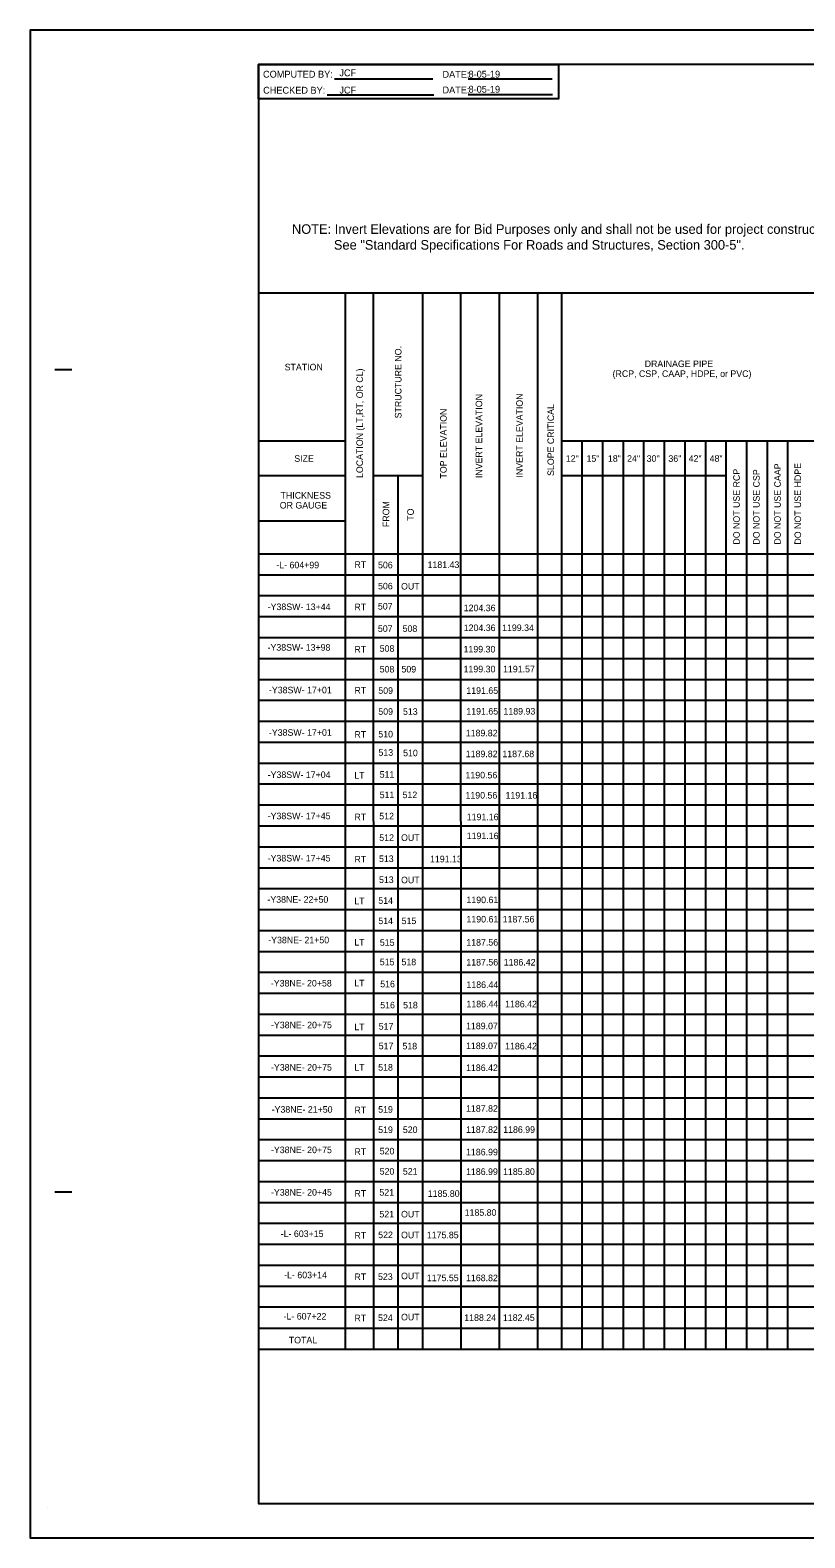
# Model space of a CAD drawing. Extents: x 809447 to 814738, y 647528 to 651206.
# Drawn here: x 811255 to 811820, y 650017 to 651117 of the extents above; entities that cross this region are included whole.
import ezdxf

# ---------------------------------------------------------------- set-up
doc = ezdxf.new("R2010")
doc.units = 0
doc.layers.add('Default', color=7, linetype='Continuous')

msp = doc.modelspace()

# ---------------------------------------------------------------- linework, layer by layer
at = {"layer": 'Default'}
for p, q in [((811476.8, 651081.5), (811548.4, 651081.5)), ((811574.2, 651081.4), (811635.6, 651081.4)), ((811471.4, 651069.8), (811549.1, 651069.8)), ((811574.3, 651069.9), (811635.7, 651069.9)), ((812921.2, 650925.1), (811421.2, 650925)), ((811484.8, 650154.3), (811484.8, 650925)), ((811505.4, 650154.3), (811505.3, 650925)), ((811541.1, 650154.3), (811541.1, 650925)), ((811569.1, 650154.3), (811569, 650925)), ((811597.1, 650154.3), (811597, 650925)), ((811625, 650154.3), (811625, 650925)), ((811642.5, 650154.3), (811642.5, 650925)), ((811272.7, 650869.4), (811285.2, 650869.4)), ((811484.8, 650817.1), (811421.2, 650817.1)), ((812160, 650817.2), (811642.5, 650817.1)), ((811657.5, 650154.3), (811657.5, 650817.1)), ((811672.5, 650154.3), (811672.5, 650817.1)), ((811687.5, 650154.3), (811687.5, 650817.1)), ((811702.5, 650154.3), (811702.5, 650817.1)), ((811717.5, 650154.3), (811717.5, 650817.1)), ((811732.5, 650154.3), (811732.5, 650817.1)), ((811747.5, 650154.3), (811747.5, 650817.1)), ((811762.5, 650154.3), (811762.5, 650817.1)), ((811777.5, 650154.3), (811777.5, 650817.1)), ((811792.5, 650154.3), (811792.5, 650817.1)), ((811807.5, 650154.3), (811807.5, 650817.1)), ((811484.8, 650791.7), (811421.2, 650791.7)), ((811541.1, 650791.7), (811505.3, 650791.7)), ((811523.3, 650154.3), (811523.2, 650791.7)), ((811762.5, 650791.8), (811642.5, 650791.7)), ((811484.8, 650758.6), (811421.2, 650758.6)), ((812921.2, 650734.7), (811421.2, 650734.7)), ((812921.2, 650719.4), (811421.2, 650719.4)), ((812921.2, 650704.1), (811421.2, 650704.1)), ((812921.2, 650688.9), (811421.2, 650688.9)), ((812921.2, 650673.6), (811421.2, 650673.6)), ((812921.2, 650658.3), (811421.2, 650658.3)), ((812921.2, 650643), (811421.2, 650643)), ((812921.2, 650627.8), (811421.2, 650627.8)), ((812921.2, 650612.5), (811421.2, 650612.5)), ((812921.2, 650597.3), (811421.2, 650597.3)), ((812921.2, 650582), (811421.2, 650582)), ((812921.2, 650566.7), (811421.2, 650566.7)), ((812921.2, 650551.5), (811421.2, 650551.5)), ((812921.2, 650536.2), (811421.2, 650536.2)), ((812921.2, 650520.9), (811421.2, 650520.9)), ((812921.2, 650505.6), (811421.2, 650505.6)), ((812921.2, 650490.4), (811421.2, 650490.4)), ((812921.2, 650475.1), (811421.2, 650475.1)), ((812921.2, 650459.8), (811421.2, 650459.8)), ((812921.2, 650444.5), (811421.2, 650444.5)), ((812921.2, 650429.3), (811421.2, 650429.3)), ((812921.2, 650414), (811421.2, 650414)), ((812921.2, 650398.8), (811421.2, 650398.8)), ((812921.2, 650383.5), (811421.2, 650383.5)), ((812921.2, 650368.3), (811421.2, 650368.3)), ((812921.2, 650353), (811421.2, 650353)), ((812921.2, 650337.8), (811421.2, 650337.8)), ((812921.2, 650322.5), (811421.2, 650322.5)), ((812921.2, 650307.2), (811421.2, 650307.2)), ((812921.2, 650291.9), (811421.2, 650291.9)), ((812921.2, 650276.7), (811421.2, 650276.7)), ((811272.7, 650269.4), (811285.2, 650269.4)), ((812921.2, 650261.4), (811421.2, 650261.4)), ((812921.2, 650246.2), (811421.2, 650246.2)), ((812921.2, 650230.9), (811421.2, 650230.9)), ((812921.2, 650215.7), (811421.2, 650215.7)), ((812921.2, 650200.4), (811421.2, 650200.4)), ((812921.2, 650185.2), (811421.2, 650185.2)), ((812921.2, 650169.6), (811421.2, 650169.6)), ((812921.2, 650154.3), (811421.2, 650154.3)), ((812921.2, 650154.3), (811421.2, 650154.3)), ((811267.7, 650039.4), (811267.7, 650039.4)), ((811421.2, 650041.9), (811421.2, 650041.9)), ((811421.2, 650041.9), (811421.2, 650041.9)), ((811421.2, 650041.9), (811421.2, 650041.9)), ((811421.2, 650041.9), (811421.2, 650041.9)), ((811421.2, 650041.9), (811421.2, 650041.9)), ((811421.2, 650041.9), (811421.2, 650041.9)), ((811421.2, 650041.9), (811421.2, 650041.9)), ((811421.2, 650041.9), (811421.2, 650041.9)), ((811421.2, 650041.9), (811421.2, 650041.9)), ((811254.7, 650016.9), (811254.7, 650016.9))]:
    msp.add_line(p, q, dxfattribs=at)
for points in [[(812938.7, 651116.9), (811254.7, 651116.9), (811254.7, 650016.9), (812938.7, 650016.9)], [(812921.2, 651091.9), (811421.2, 651091.9), (811421.2, 650041.9), (812921.2, 650041.9)], [(811421.2, 651091.9), (811640.2, 651091.9), (811640.2, 651066.9), (811421.2, 651066.9)]]:
    msp.add_lwpolyline(points, close=True, dxfattribs=at)

# ---------------------------------------------------------------- texts
for s, height, rotation, p in [('COMPUTED BY:', 5, 360, (811424.6, 651082.3)), ('JCF', 5, 360, (811480.3, 651083.3)), ('DATE:', 5, 360, (811555.5, 651082.2)), ('CHECKED BY:', 5, 360, (811424.7, 651070.6)), ('JCF', 5, 360, (811480.3, 651070.7)), ('DATE:', 5, 360, (811555.5, 651070.8)), ('STRUCTURE NO.', 4.8, 90, (811525.6, 650833.7)), ('STATION', 4.8, 360, (811440.4, 650868.7)), ('LOCATION (LT,RT, OR CL)', 4.8, 90, (811497.5, 650790.2)), ('INVERT ELEVATION', 4.8, 90, (811584.5, 650790.1)), ('INVERT ELEVATION', 4.8, 90, (811614.1, 650790.5)), ('TOP ELEVATION', 4.8, 90, (811558.6, 650789.8)), ('SLOPE CRITICAL', 4.8, 90, (811636.9, 650791.7)), ('DO NOT USE RCP', 4.8, 90, (811772.4, 650741.6)), ('DO NOT USE CSP', 4.8, 90, (811786.9, 650741.6)), ('DO NOT USE CAAP', 4.8, 90, (811802.3, 650741.6)), ('DO NOT USE HDPE', 4.8, 90, (811817.1, 650741.6)), ('FROM', 4.8, 90, (811516.7, 650754.4)), ('TO', 4.8, 90, (811534.6, 650759))]:
    msp.add_text(s, height=height, rotation=rotation, dxfattribs=at).set_placement(p)
for s, height, p in [('8-05-19', 5, (811574.5, 651082.3)), ('8-05-19', 5, (811574.5, 651071.3)), ('NOTE: Invert Elevations are for Bid Purposes only and shall not be used for project construction stakeout.', 7, (811445.7, 650968.3)), ('See "Standard Specifications For Roads and Structures, Section 300-5".', 7, (811476.3, 650956.8)), ('DRAINAGE PIPE', 4.8, (811703, 650871.1)), ('(RCP, CSP, CAAP, HDPE, or PVC)', 4.8, (811679.6, 650863.9)), ('SIZE', 4.8, (811447.4, 650802)), ('12"', 4.8, (811645.5, 650802)), ('15"', 4.8, (811660.6, 650802)), ('18"', 4.8, (811676.2, 650802)), ('24"', 4.8, (811690.2, 650802)), ('30"', 4.8, (811704.5, 650802)), ('36"', 4.8, (811720.3, 650802)), ('42"', 4.8, (811735.1, 650802)), ('48"', 4.8, (811750.4, 650802)), ('OR GAUGE', 4.8, (811436.8, 650767.9)), ('THICKNESS', 4.8, (811437.4, 650775.1)), ('-L- 604+99', 4.8, (811434.3, 650724.3)), ('RT', 4.8, (811491.3, 650724.6)), ('506', 4.8, (811508.5, 650724.3)), ('1181.43', 4.8, (811544.6, 650724.5)), ('506', 4.8, (811508.5, 650708.9)), ('OUT', 4.8, (811525.3, 650708.8)), ('-Y38SW- 13+44', 4.8, (811428, 650693.8)), ('RT', 4.8, (811491.3, 650693.7)), ('507', 4.8, (811508.4, 650694.2)), ('1204.36', 4.8, (811571, 650693)), ('1204.36', 4.8, (811571, 650678.5)), ('1199.34', 4.8, (811599, 650678.5)), ('507', 4.8, (811508.4, 650677.9)), ('508', 4.8, (811526.4, 650677.9)), ('-Y38SW- 13+98', 4.8, (811427.9, 650664.2)), ('RT', 4.8, (811491.3, 650662.8)), ('508', 4.8, (811509.7, 650663.4)), ('1199.30', 4.8, (811570.9, 650662.9)), ('508', 4.8, (811509.7, 650648.3)), ('509', 4.8, (811525.6, 650648.3)), ('1199.30', 4.8, (811570.9, 650648.4)), ('1191.57', 4.8, (811599.7, 650648.4)), ('-Y38SW- 17+01', 4.8, (811428.9, 650633.1)), ('RT', 4.8, (811491.3, 650632.9)), ('509', 4.8, (811508.7, 650632.7)), ('1191.65', 4.8, (811572.9, 650632.7)), ('509', 4.8, (811508.7, 650617.4)), ('513', 4.8, (811526.7, 650617.4)), ('1191.65', 4.8, (811572.9, 650617.6)), ('1189.93', 4.8, (811600, 650617.6)), ('-Y38SW- 17+01', 4.8, (811428.9, 650602.1)), ('1189.82', 4.8, (811572.5, 650601.7)), ('RT', 4.8, (811491.3, 650600.7)), ('510', 4.8, (811508.7, 650600.9)), ('513', 4.8, (811508.8, 650587.5)), ('510', 4.8, (811526.8, 650587.2)), ('1189.82', 4.8, (811572.5, 650586.5)), ('1187.68', 4.8, (811599.2, 650586.5)), ('-Y38SW- 17+04', 4.8, (811428, 650571.3)), ('LT', 4.8, (811491.2, 650570.9)), ('511', 4.8, (811509.7, 650571.5)), ('1190.56', 4.8, (811572.3, 650571)), ('511', 4.8, (811509.7, 650556.6)), ('512', 4.8, (811526.4, 650556.6)), ('1190.56', 4.8, (811572.3, 650556.3)), ('1191.16', 4.8, (811601.5, 650556.3)), ('-Y38SW- 17+45', 4.8, (811428, 650541.2)), ('RT', 4.8, (811491.3, 650540.5)), ('512', 4.8, (811509.4, 650541.1)), ('1191.16', 4.8, (811573.2, 650540.5)), ('512', 4.8, (811509.4, 650525.4)), ('OUT', 4.8, (811525.3, 650525.4)), ('1191.16', 4.8, (811573.2, 650526.7)), ('-Y38SW- 17+45', 4.8, (811428, 650510.4)), ('RT', 4.8, (811491.3, 650509.7)), ('513', 4.8, (811509.2, 650510)), ('1191.13', 4.8, (811546.4, 650509.8)), ('513', 4.8, (811509.2, 650494.7)), ('OUT', 4.8, (811525.3, 650494.5)), ('-Y38NE- 22+50', 4.8, (811427.8, 650480.3)), ('LT', 4.8, (811491.2, 650479.2)), ('514', 4.8, (811508.7, 650479.5)), ('1190.61', 4.8, (811573, 650480)), ('514', 4.8, (811508.7, 650464.7)), ('515', 4.8, (811525.7, 650464.7)), ('1190.61', 4.8, (811573, 650465.9)), ('1187.56', 4.8, (811599.4, 650465.9)), ('-Y38NE- 21+50', 4.8, (811428.4, 650450.7)), ('LT', 4.8, (811491.2, 650449.1)), ('515', 4.8, (811509.8, 650448.9)), ('1187.56', 4.8, (811572.9, 650449)), ('515', 4.8, (811509.8, 650434.7)), ('518', 4.8, (811525.6, 650434.7)), ('1187.56', 4.8, (811572.9, 650434.5)), ('1186.42', 4.8, (811600.2, 650434.5)), ('-Y38NE- 20+58', 4.8, (811430.3, 650419.2)), ('LT', 4.8, (811491.2, 650419.3)), ('516', 4.8, (811510.1, 650418.6)), ('1186.44', 4.8, (811573, 650418.1)), ('516', 4.8, (811510.1, 650403.2)), ('518', 4.8, (811526.8, 650403.2)), ('1186.44', 4.8, (811573, 650404)), ('1186.42', 4.8, (811601.2, 650404)), ('-Y38NE- 20+75', 4.8, (811430.4, 650388.7)), ('LT', 4.8, (811491.2, 650387.3)), ('517', 4.8, (811509, 650387.7)), ('1189.07', 4.8, (811572.7, 650388)), ('517', 4.8, (811509, 650373.4)), ('518', 4.8, (811526.3, 650373.3)), ('1189.07', 4.8, (811572.7, 650373.5)), ('1186.42', 4.8, (811601.2, 650373.3)), ('-Y38NE- 20+75', 4.8, (811430.4, 650357.8)), ('LT', 4.8, (811491.2, 650357.8)), ('518', 4.8, (811508.6, 650357.8)), ('1186.42', 4.8, (811572.7, 650357.5)), ('-Y38NE- 21+50', 4.8, (811430.9, 650327.1)), ('RT', 4.8, (811491.3, 650326.7)), ('519', 4.8, (811508.6, 650327.1)), ('1187.82', 4.8, (811572.7, 650327.8)), ('519', 4.8, (811508.6, 650312.3)), ('520', 4.8, (811526.6, 650312.3)), ('1187.82', 4.8, (811572.7, 650312.4)), ('1186.99', 4.8, (811599.8, 650312.4)), ('-Y38NE- 20+75', 4.8, (811430.4, 650297.6)), ('RT', 4.8, (811491.3, 650296.3)), ('520', 4.8, (811509.7, 650296.7)), ('1186.99', 4.8, (811572.7, 650296)), ('520', 4.8, (811509.7, 650281.9)), ('521', 4.8, (811526.6, 650281.9)), ('1186.99', 4.8, (811572.7, 650281.7)), ('1185.80', 4.8, (811599.7, 650281.7)), ('-Y38NE- 20+45', 4.8, (811430.4, 650266.6)), ('RT', 4.8, (811491.3, 650265.8)), ('521', 4.8, (811509.5, 650266.6)), ('1185.80', 4.8, (811544.8, 650265.7)), ('521', 4.8, (811509.5, 650250.7)), ('OUT', 4.8, (811525.3, 650250.7)), ('1185.80', 4.8, (811571.7, 650251.9)), ('-L- 603+15', 4.8, (811437.5, 650236.4)), ('RT', 4.8, (811491.3, 650235.2)), ('522', 4.8, (811508.6, 650235.6)), ('OUT', 4.8, (811525.3, 650235.5)), ('1175.85', 4.8, (811544.1, 650235.5)), ('-L- 603+14', 4.8, (811440, 650206.3)), ('523', 4.8, (811508.5, 650205.1)), ('OUT', 4.8, (811525.3, 650205.6)), ('RT', 4.8, (811491.3, 650205)), ('1175.55', 4.8, (811544.1, 650204.2)), ('1168.82', 4.8, (811572.7, 650204.2)), ('-L- 607+22', 4.8, (811439.6, 650176.2)), ('RT', 4.8, (811491.3, 650174.9)), ('524', 4.8, (811508.5, 650175.1)), ('OUT', 4.8, (811525.3, 650175.6)), ('1188.24', 4.8, (811571.4, 650175.2)), ('1182.45', 4.8, (811599.6, 650175.2)), ('TOTAL', 4.8, (811443.4, 650158.8))]:
    msp.add_text(s, height=height, dxfattribs=at).set_placement(p)

doc.saveas('drawing.dxf')
